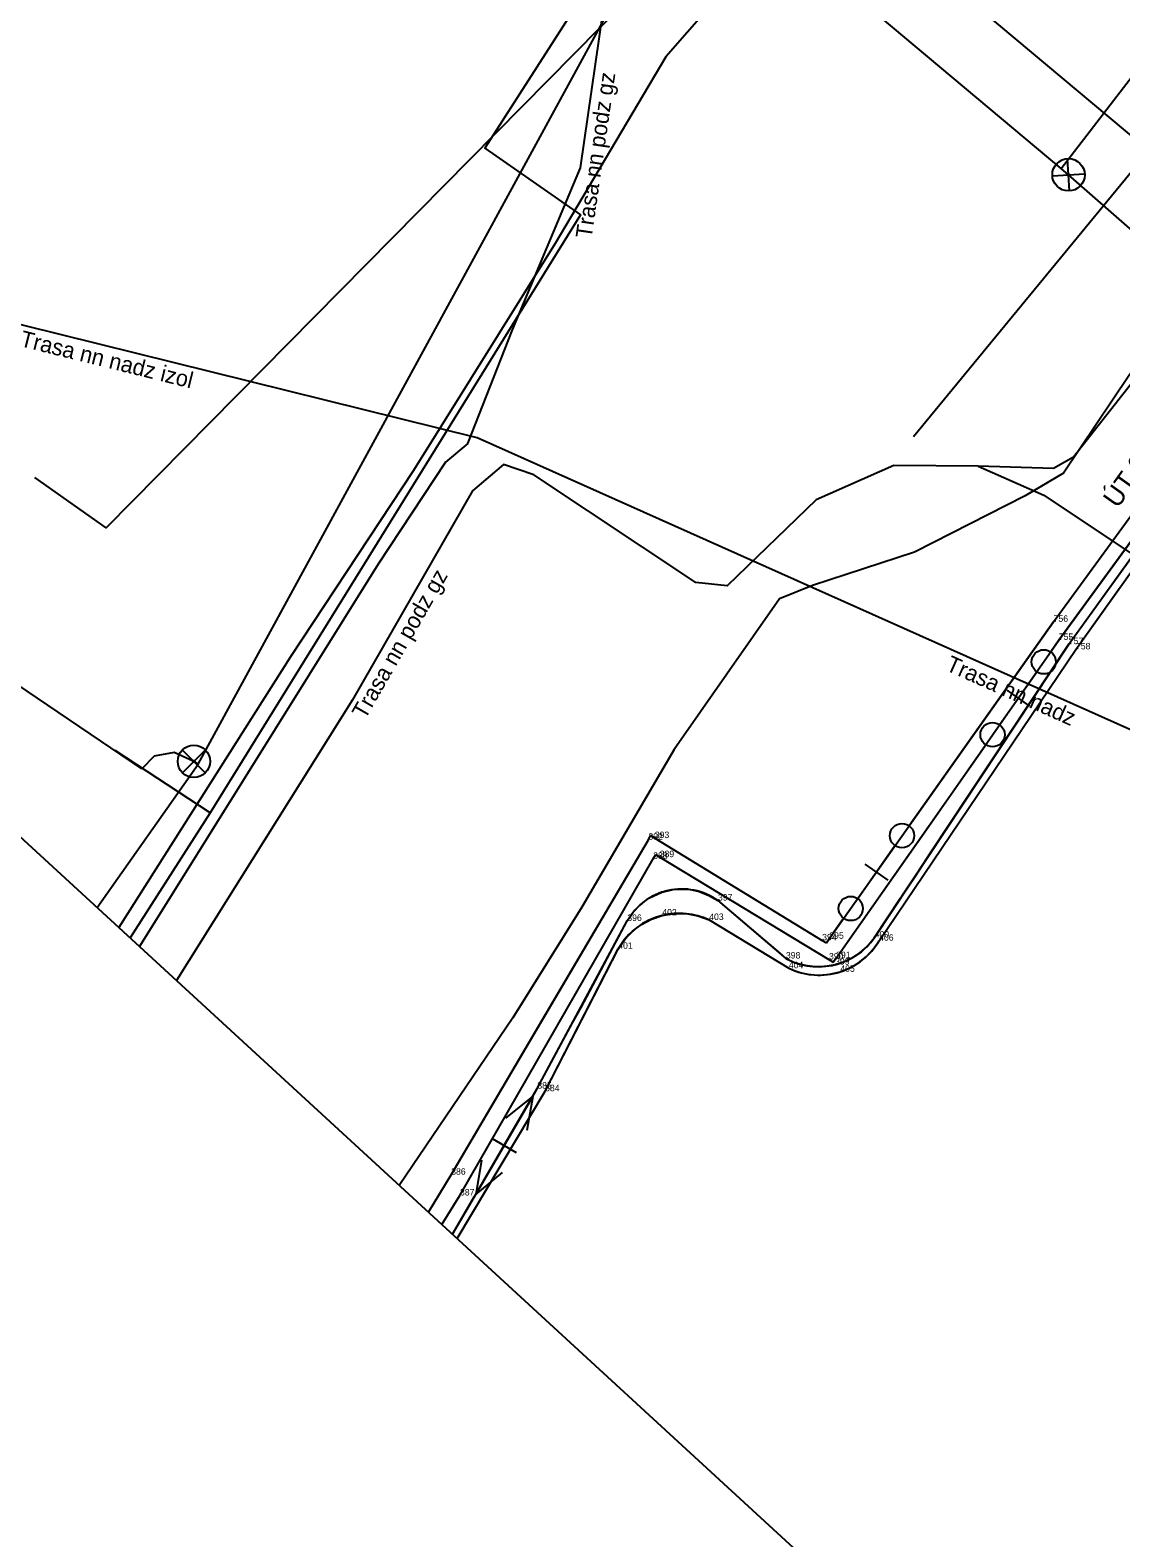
# Model space of a CAD drawing. Extents: x -494395 to -49419, y -1126982 to -112683.
# Drawn here: x -494348.75 to -494315.05, y -1126911.61 to -1126865.03 of the extents above; entities that cross this region are included whole.
import ezdxf

# ---------------------------------------------------------------- set-up
doc = ezdxf.new("R2010")
doc.units = 0
for name, color, linetype in [('Vrstva 1', 7, 'Continuous'), ('Vrstva 11', 7, 'Continuous'), ('Vrstva 12', 7, 'Continuous'), ('Vrstva 20', 7, 'Continuous'), ('Vrstva 22', 7, 'Continuous'), ('Vrstva 35', 7, 'Continuous'), ('Vrstva 41', 7, 'Continuous'), ('Vrstva 45', 7, 'Continuous'), ('Vrstva 49', 7, 'Continuous'), ('Vrstva 5', 7, 'Continuous'), ('Vrstva 9', 7, 'Continuous')]:
    doc.layers.add(name, color=color, linetype=linetype)

msp = doc.modelspace()

# ---------------------------------------------------------------- linework, layer by layer
at = {"layer": 'Vrstva 1'}
for points in [[(-494182.319, -1126891.398), (-494324.599, -1126787.796), (-494395.386, -1126847.35), (-494248.552, -1126982.359)], [(-494328.43, -1126854.34), (-494329.69, -1126855.78), (-494325.53, -1126859.26), (-494313.03, -1126869.73), (-494305.67, -1126875.89), (-494291.14, -1126888.24), (-494277.78, -1126899.58), (-494263.78, -1126911.3)], [(-494325.53, -1126859.26), (-494346.4, -1126880.41), (-494348.6, -1126878.85)]]:
    msp.add_lwpolyline(points, dxfattribs=at)
at = {"layer": 'Vrstva 11'}
msp.add_lwpolyline([(-494309.28, -1126865.93), (-494310.34, -1126868.6), (-494311.33, -1126871.01), (-494314.81, -1126875.71), (-494316.82, -1126878.72), (-494318.01, -1126879.42), (-494321.43, -1126881.16), (-494324.58, -1126882.19), (-494325.6, -1126882.6), (-494328.85, -1126887.25), (-494331.71, -1126892.12), (-494333.84, -1126895.54), (-494337.345, -1126900.717)], dxfattribs=at)
at = {"layer": 'Vrstva 12'}
for points in [[(-494323.91, -1126859.91), (-494329.11, -1126865.86)], [(-494329.11, -1126865.86), (-494332.53, -1126871.62), (-494336.91, -1126878.64), (-494340.71, -1126884.39), (-494346.005, -1126892.754)]]:
    msp.add_lwpolyline(points, dxfattribs=at)
at = {"layer": 'Vrstva 20'}
for p, q in [((-494316.901, -1126869.31), (-494328.074, -1126859.924)), ((-494316.67, -1126869.5), (-494316.901, -1126869.31)), ((-494345.3, -1126887.85), (-494351.716, -1126883.507))]:
    msp.add_line(p, q, dxfattribs=at)
for points in [[(-494316.901, -1126869.31), (-494312.976, -1126864.212), (-494296.263, -1126844.814), (-494282.714, -1126828.712), (-494277.399, -1126822.165)], [(-494346.681, -1126892.133), (-494343.56, -1126887.71), (-494328.57, -1126860.21)], [(-494260.78, -1126914.53), (-494284.601, -1126896.199), (-494309.435, -1126875.839), (-494316.67, -1126869.5)], [(-494343.56, -1126887.71), (-494343.69, -1126887.62), (-494344.3, -1126887.35), (-494344.92, -1126887.46), (-494345.3, -1126887.85)]]:
    msp.add_lwpolyline(points, dxfattribs=at)
at = {"layer": 'Vrstva 22'}
for p, q in [((-494316.637, -1126869.994), (-494316.703, -1126869.006)), ((-494317.164, -1126869.533), (-494316.176, -1126869.467)), ((-494344.04, -1126887.97), (-494343.34, -1126887.27)), ((-494343.34, -1126887.97), (-494344.04, -1126887.27))]:
    msp.add_line(p, q, dxfattribs=at)
for centre, radius in [((-494316.67, -1126869.5), 0.5), ((-494316.67, -1126869.5), 0.025), ((-494343.69, -1126887.62), 0.5), ((-494343.69, -1126887.62), 0.025)]:
    msp.add_circle(centre, radius, dxfattribs=at)
at = {"layer": 'Vrstva 35'}
for points in [[(-494300.66, -1126826.53), (-494304.08, -1126829.77), (-494307, -1126833.05), (-494310.38, -1126837.7), (-494312.57, -1126839.92), (-494316.3, -1126844.63), (-494317.42, -1126846.17), (-494319.02, -1126847.69), (-494327.08, -1126857.66), (-494327.96, -1126857.89), (-494330.7, -1126861.76), (-494332.02, -1126864.51), (-494334.7, -1126868.68), (-494331.75, -1126870.74), (-494343.19, -1126889.21), (-494346.12, -1126887.28)], [(-494343.19, -1126889.21), (-494345.658, -1126893.074)]]:
    msp.add_lwpolyline(points, dxfattribs=at)
at = {"layer": 'Vrstva 41'}
msp.add_lwpolyline([(-494276.436, -1126822.866), (-494276.44, -1126822.87), (-494321.46, -1126877.59)], dxfattribs=at)
at = {"layer": 'Vrstva 45'}
for p, q in [((-494317.13, -1126883.31), (-494310.07, -1126873.6)), ((-494317.13, -1126883.31), (-494310.07, -1126873.6)), ((-494316.97, -1126883.87), (-494309.9, -1126874.17)), ((-494316.97, -1126883.88), (-494309.9, -1126874.18)), ((-494316.44, -1126884.16), (-494309.95, -1126875.02)), ((-494316.66, -1126884), (-494312.43, -1126878.12)), ((-494315.1, -1126881.83), (-494313.49, -1126879.59)), ((-494316.66, -1126884), (-494315.1, -1126881.83)), ((-494316.44, -1126884.16), (-494315.07, -1126882.24)), ((-494324.06, -1126893.1), (-494317.13, -1126883.31)), ((-494317.13, -1126883.31), (-494321.59, -1126889.61)), ((-494317.13, -1126883.31), (-494317.13, -1126883.31)), ((-494316.66, -1126884), (-494322.66, -1126893.06)), ((-494322.52, -1126893.16), (-494316.44, -1126884.16)), ((-494322.52, -1126893.16), (-494316.44, -1126884.16)), ((-494320.93, -1126890.45), (-494316.66, -1126884)), ((-494319.01, -1126886.79), (-494316.97, -1126883.88)), ((-494317.2, -1126884.2), (-494316.97, -1126883.87)), ((-494316.97, -1126883.87), (-494316.97, -1126883.87)), ((-494316.66, -1126884), (-494316.66, -1126884)), ((-494316.44, -1126884.16), (-494316.44, -1126884.16)), ((-494318.802, -1126886.49), (-494317.653, -1126884.854)), ((-494318.578, -1126885.424), (-494317.875, -1126885.919)), ((-494320.99, -1126889.62), (-494319.01, -1126886.79)), ((-494323.85, -1126893.7), (-494319.26, -1126887.15)), ((-494323.85, -1126893.7), (-494320.99, -1126889.62)), ((-494335.74, -1126900.39), (-494329.65, -1126890.04)), ((-494332.93, -1126895.61), (-494329.65, -1126890.04)), ((-494329.65, -1126890.04), (-494329.58, -1126889.91)), ((-494329.65, -1126890.04), (-494329.58, -1126889.91)), ((-494329.65, -1126890.04), (-494329.65, -1126890.04)), ((-494329.45, -1126889.99), (-494329.58, -1126889.91)), ((-494329.58, -1126889.91), (-494329.58, -1126889.91)), ((-494329.58, -1126889.91), (-494329.45, -1126889.99)), ((-494329.45, -1126889.99), (-494329.45, -1126889.99)), ((-494329.45, -1126889.99), (-494324.28, -1126893.15)), ((-494329.45, -1126889.99), (-494324.28, -1126893.15)), ((-494323.182, -1126891.86), (-494322.033, -1126890.224)), ((-494335.47, -1126901.03), (-494329.5, -1126890.63)), ((-494335.47, -1126901.03), (-494329.5, -1126890.63)), ((-494329.5, -1126890.63), (-494329.42, -1126890.5)), ((-494329.5, -1126890.63), (-494329.42, -1126890.5)), ((-494329.5, -1126890.63), (-494329.5, -1126890.63)), ((-494329.3, -1126890.58), (-494329.42, -1126890.5)), ((-494329.42, -1126890.5), (-494329.42, -1126890.5)), ((-494329.42, -1126890.5), (-494329.3, -1126890.58)), ((-494329.3, -1126890.58), (-494329.3, -1126890.58)), ((-494329.3, -1126890.58), (-494324.07, -1126893.74)), ((-494329.3, -1126890.58), (-494324.07, -1126893.74)), ((-494322.958, -1126890.794), (-494322.255, -1126891.289)), ((-494321.41, -1126891.18), (-494320.93, -1126890.45)), ((-494321.86, -1126891.85), (-494321.41, -1126891.18)), ((-494329.64, -1126891.85), (-494329.35, -1126891.71)), ((-494329.35, -1126891.71), (-494329.22, -1126891.66)), ((-494329.22, -1126891.66), (-494328.88, -1126891.58)), ((-494329.05, -1126891.61), (-494329.05, -1126891.61)), ((-494328.88, -1126891.58), (-494328.64, -1126891.57)), ((-494328.64, -1126891.57), (-494328.4, -1126891.57)), ((-494328.4, -1126891.57), (-494328.08, -1126891.64)), ((-494328.08, -1126891.64), (-494327.78, -1126891.76)), ((-494330.12, -1126892.28), (-494329.9, -1126892.05)), ((-494329.9, -1126892.05), (-494329.64, -1126891.85)), ((-494327.78, -1126891.76), (-494327.5, -1126891.92)), ((-494327.5, -1126891.92), (-494327.5, -1126891.92)), ((-494327.5, -1126891.92), (-494325.4, -1126893.71)), ((-494327.5, -1126891.92), (-494326.68, -1126892.62)), ((-494322.66, -1126893.06), (-494321.86, -1126891.85)), ((-494333.08, -1126897.73), (-494330.3, -1126892.55)), ((-494331.73, -1126895.22), (-494330.3, -1126892.55)), ((-494330.3, -1126892.55), (-494330.12, -1126892.28)), ((-494330.3, -1126892.55), (-494330.3, -1126892.55)), ((-494330.14, -1126892.87), (-494329.86, -1126892.66)), ((-494329.86, -1126892.66), (-494329.55, -1126892.49)), ((-494329.55, -1126892.49), (-494329.22, -1126892.38)), ((-494329.22, -1126892.38), (-494328.85, -1126892.32)), ((-494329.22, -1126892.38), (-494329.22, -1126892.38)), ((-494328.85, -1126892.32), (-494328.48, -1126892.32)), ((-494328.48, -1126892.32), (-494328.12, -1126892.39)), ((-494328.12, -1126892.39), (-494327.77, -1126892.52)), ((-494327.77, -1126892.52), (-494327.77, -1126892.52)), ((-494327.77, -1126892.52), (-494325.31, -1126894.01)), ((-494327.77, -1126892.52), (-494325.31, -1126894.01)), ((-494326.68, -1126892.62), (-494325.52, -1126893.61)), ((-494323.65, -1126892.52), (-494324.06, -1126893.1)), ((-494330.58, -1126893.42), (-494330.38, -1126893.12)), ((-494330.38, -1126893.12), (-494330.14, -1126892.87)), ((-494324.06, -1126893.1), (-494324.15, -1126893.23)), ((-494324.15, -1126893.23), (-494324.06, -1126893.1)), ((-494324.06, -1126893.1), (-494324.06, -1126893.1)), ((-494322.85, -1126893.29), (-494322.66, -1126893.06)), ((-494322.66, -1126893.06), (-494322.66, -1126893.06)), ((-494332.84, -1126897.81), (-494330.58, -1126893.41)), ((-494332.84, -1126897.81), (-494330.58, -1126893.42)), ((-494330.58, -1126893.41), (-494330.58, -1126893.41)), ((-494324.28, -1126893.15), (-494324.28, -1126893.15)), ((-494324.28, -1126893.15), (-494324.15, -1126893.23)), ((-494324.28, -1126893.15), (-494324.15, -1126893.23)), ((-494324.15, -1126893.23), (-494324.15, -1126893.23)), ((-494323.32, -1126893.67), (-494323.07, -1126893.5)), ((-494323.07, -1126893.5), (-494322.85, -1126893.29)), ((-494322.91, -1126893.65), (-494322.7, -1126893.42)), ((-494322.7, -1126893.42), (-494322.52, -1126893.16)), ((-494322.52, -1126893.16), (-494322.52, -1126893.16)), ((-494325.52, -1126893.61), (-494325.4, -1126893.71)), ((-494325.4, -1126893.71), (-494325.4, -1126893.71)), ((-494325.4, -1126893.71), (-494325.11, -1126893.84)), ((-494325.31, -1126894.01), (-494325.31, -1126894.01)), ((-494325.31, -1126894.01), (-494325.01, -1126894.13)), ((-494325.11, -1126893.84), (-494324.81, -1126893.92)), ((-494324.81, -1126893.92), (-494324.5, -1126893.96)), ((-494324.5, -1126893.96), (-494324.23, -1126893.95)), ((-494324.23, -1126893.95), (-494324.19, -1126893.95)), ((-494324.19, -1126893.95), (-494323.88, -1126893.9)), ((-494324.07, -1126893.74), (-494324.07, -1126893.74)), ((-494324.07, -1126893.74), (-494323.94, -1126893.82)), ((-494324.07, -1126893.74), (-494323.94, -1126893.82)), ((-494323.85, -1126893.7), (-494323.94, -1126893.82)), ((-494323.94, -1126893.82), (-494323.85, -1126893.7)), ((-494323.94, -1126893.82), (-494323.94, -1126893.82)), ((-494323.88, -1126893.9), (-494323.59, -1126893.8)), ((-494323.88, -1126893.9), (-494323.88, -1126893.9)), ((-494323.85, -1126893.7), (-494323.85, -1126893.7)), ((-494323.72, -1126894.12), (-494323.43, -1126894)), ((-494323.59, -1126893.8), (-494323.32, -1126893.67)), ((-494323.43, -1126894), (-494323.16, -1126893.84)), ((-494323.16, -1126893.84), (-494322.91, -1126893.65)), ((-494325.01, -1126894.13), (-494324.69, -1126894.2)), ((-494324.69, -1126894.2), (-494324.36, -1126894.22)), ((-494324.36, -1126894.22), (-494324.04, -1126894.19)), ((-494324.04, -1126894.19), (-494323.72, -1126894.12)), ((-494323.72, -1126894.12), (-494323.72, -1126894.12)), ((-494331.99, -1126895.7), (-494331.73, -1126895.22)), ((-494335.74, -1126900.39), (-494332.93, -1126895.61)), ((-494333.08, -1126897.73), (-494331.99, -1126895.7)), ((-494333.93, -1126899.18), (-494333.08, -1126897.73)), ((-494333.18, -1126897.9), (-494333.08, -1126897.73)), ((-494333.08, -1126897.73), (-494333.08, -1126897.73)), ((-494335.556, -1126902.362), (-494332.84, -1126897.81)), ((-494335.556, -1126902.362), (-494332.84, -1126897.81)), ((-494334.983, -1126900.996), (-494333.22, -1126897.97)), ((-494332.84, -1126897.81), (-494332.84, -1126897.81)), ((-494335.03, -1126901.08), (-494333.93, -1126899.18)), ((-494334.472, -1126899.267), (-494333.731, -1126899.7)), ((-494336.444, -1126901.545), (-494335.74, -1126900.39)), ((-494336.444, -1126901.545), (-494335.74, -1126900.39)), ((-494335.74, -1126900.39), (-494335.74, -1126900.39)), ((-494336.026, -1126901.929), (-494335.47, -1126901.03)), ((-494336.025, -1126901.93), (-494335.47, -1126901.03)), ((-494335.47, -1126901.03), (-494335.47, -1126901.03)), ((-494335.703, -1126902.227), (-494335.03, -1126901.07)), ((-494335.702, -1126902.227), (-494335.03, -1126901.08))]:
    msp.add_line(p, q, dxfattribs=at)
for points in [[(-494334.048, -1126898.646), (-494333.22, -1126897.97), (-494333.401, -1126899.023)], [(-494334.803, -1126899.941), (-494334.983, -1126900.996), (-494334.155, -1126900.32)]]:
    msp.add_lwpolyline(points, dxfattribs=at)
for centre in [(-494317.435, -1126884.546), (-494319.017, -1126886.796), (-494321.815, -1126889.917), (-494323.397, -1126892.166)]:
    msp.add_circle(centre, 0.375, dxfattribs=at)
for centre, radius, start, end in [((-494328.62, -1126893.482), 1.921, 102.9206, 150.9657), ((-494328.617, -1126893.49), 1.927, 54.5583, 102.6788), ((-494328.698, -1126894.482), 2.166, 103.9444, 150.3328), ((-494328.692, -1126894.488), 2.173, 64.9013, 104.0689), ((-494324.399, -1126891.84), 2.125, 284.15, 324.9468), ((-494324.387, -1126892.056), 2.169, 287.9097, 329.4099), ((-494324.393, -1126891.833), 2.13, 241.8027, 283.9473), ((-494324.376, -1126892.059), 2.163, 244.4245, 287.6604)]:
    msp.add_arc(centre, radius, start, end, dxfattribs=at)
at = {"layer": 'Vrstva 5'}
for points in [[(-494290.944, -1126841.251), (-494293.803, -1126844.41), (-494297.475, -1126847.939), (-494298.803, -1126849.6), (-494299.62, -1126852.341), (-494303.181, -1126857.248), (-494305.877, -1126860.459), (-494308.341, -1126862.457), (-494309.981, -1126864.466), (-494310.59, -1126867.15), (-494310.629, -1126870.07), (-494311.184, -1126871.451), (-494316.519, -1126878.222), (-494317.129, -1126878.573), (-494319.457, -1126878.505)], [(-494335.227, -1126877.797), (-494333.852, -1126874.288), (-494331.744, -1126869.283), (-494330.931, -1126863.657), (-494331.988, -1126861.664), (-494334.122, -1126859.593), (-494334.819, -1126859.137)], [(-494334.936, -1126877.626), (-494356.021, -1126872.401)], [(-494300.538, -1126892.997), (-494334.936, -1126877.626)], [(-494335.227, -1126877.797), (-494335.918, -1126878.381), (-494337.995, -1126881.53), (-494345.369, -1126893.339)], [(-494319.457, -1126878.505), (-494322.066, -1126878.479), (-494324.468, -1126879.541), (-494327.219, -1126882.198), (-494328.179, -1126882.09), (-494333.188, -1126878.773), (-494334.12, -1126878.448), (-494335.082, -1126879.266), (-494338.788, -1126885.718), (-494344.231, -1126894.385)], [(-494319.457, -1126878.505), (-494317.433, -1126879.399), (-494313.525, -1126882.005), (-494307.398, -1126886.781), (-494305.797, -1126887.089), (-494303.14, -1126887.419), (-494302.78, -1126887.349)]]:
    msp.add_lwpolyline(points, dxfattribs=at)

# ---------------------------------------------------------------- texts
at = {"layer": 'Vrstva 49'}
msp.add_text('ÚT 2x125/225', height=0.6, rotation=54.6227, dxfattribs=at).set_placement((-494315.154, -1126879.831))
for s, p in [('756', (-494317.13, -1126883.31)), ('755', (-494316.97, -1126883.87)), ('757', (-494316.66, -1126884)), ('758', (-494316.44, -1126884.16)), ('392', (-494329.65, -1126890.04)), ('393', (-494329.45, -1126889.99)), ('388', (-494329.5, -1126890.63)), ('389', (-494329.3, -1126890.58)), ('397', (-494327.5, -1126891.92)), ('402', (-494329.22, -1126892.38)), ('396', (-494330.3, -1126892.55)), ('403', (-494327.77, -1126892.52)), ('394', (-494324.28, -1126893.15)), ('395', (-494324.06, -1126893.1)), ('400', (-494322.66, -1126893.06)), ('406', (-494322.52, -1126893.16)), ('401', (-494330.58, -1126893.41)), ('398', (-494325.4, -1126893.71)), ('390', (-494324.07, -1126893.74)), ('391', (-494323.85, -1126893.7)), ('404', (-494325.31, -1126894.01)), ('399', (-494323.88, -1126893.9)), ('405', (-494323.72, -1126894.12)), ('385', (-494333.08, -1126897.73)), ('384', (-494332.84, -1126897.81)), ('386', (-494335.74, -1126900.39)), ('387', (-494335.47, -1126901.03))]:
    msp.add_text(s, height=0.2, dxfattribs=at).set_placement(p)
at = {"layer": 'Vrstva 9'}
for s, rotation, p in [('Trasa nn podz gz', 81.7772, (-494331.405, -1126871.484)), ('Trasa nn nadz izol', 346.0807, (-494349.087, -1126874.789)), ('Trasa nn podz gz', 60.1257, (-494338.4, -1126886.347)), ('Trasa nn nadz', 335.9227, (-494320.494, -1126884.792))]:
    msp.add_text(s, height=0.5, rotation=rotation, dxfattribs=at).set_placement(p)

doc.saveas('drawing.dxf')
